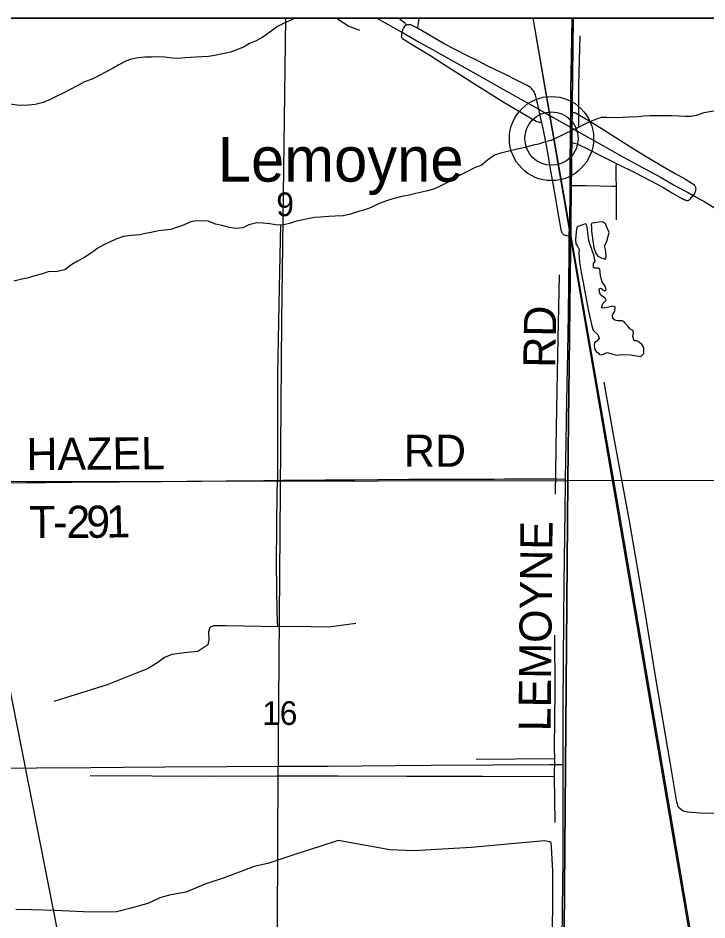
# Model space of a CAD drawing. Extents: x 0 to 34, y 0 to 22.
# Drawn here: x 3.546 to 4.765, y 19.306 to 20.9 of the extents above; entities that cross this region are included whole.
import ezdxf

# ---------------------------------------------------------------- set-up
doc = ezdxf.new("R2010")
doc.units = 0
for name, color, linetype in [('GM_X_City_Street', 7, 'Continuous'), ('GM_X_Minor_Lake', 7, 'Continuous'), ('GM_X_Minor_River', 7, 'Continuous'), ('GM_X_Rail_Line', 7, 'Continuous'), ('GM_X_Section', 7, 'Continuous'), ('GM_X_Section_Text', 7, 'Continuous'), ('GM_X_Township_Road', 7, 'Continuous'), ('GM_X_Township_Road_Text', 7, 'Continuous'), ('GM_X_Unincorporated', 7, 'Continuous'), ('GM_X_Unincorporated_Location', 7, 'Continuous'), ('GM_X_Unincorporated_Text', 7, 'Continuous'), ('GM_X_US_Route', 7, 'Continuous'), ('SH_Cut_Line', 7, 'Continuous'), ('SH_Data', 7, 'Continuous')]:
    doc.layers.add(name, color=color, linetype=linetype)

msp = doc.modelspace()

# ---------------------------------------------------------------- linework, layer by layer
at = {"layer": 'GM_X_City_Street'}
for points in [[(4.528, 20.9), (3.5146, 20.9), (3.5083, 20.0811), (4.5187, 20.0828)], [(5.527, 20.9), (4.528, 20.9), (4.5187, 20.0828), (5.5144, 20.0832)]]:
    msp.add_lwpolyline(points, close=True, dxfattribs=at)
at = {"layer": 'GM_X_Minor_Lake'}
for p, q in [((4.5559, 20.507), (4.5531, 20.5302)), ((4.5886, 20.5092), (4.5894, 20.5123))]:
    msp.add_line(p, q, dxfattribs=at)
for points in [[(4.5531, 20.5302), (4.5517, 20.5352), (4.5491, 20.5364), (4.5437, 20.5342), (4.5384, 20.5321), (4.5353, 20.531), (4.5341, 20.5269), (4.5331, 20.5159), (4.5325, 20.508), (4.5331, 20.5011), (4.5356, 20.4969), (4.5385, 20.4911), (4.5384, 20.485), (4.5385, 20.4763), (4.5395, 20.4687), (4.5424, 20.4508), (4.5458, 20.4325), (4.5491, 20.413), (4.5518, 20.4005), (4.5555, 20.3818), (4.5579, 20.3711), (4.5613, 20.3558), (4.5637, 20.3482), (4.5663, 20.3451), (4.5715, 20.3404), (4.574, 20.3335), (4.5697, 20.3291), (4.5662, 20.3265), (4.565, 20.3223), (4.566, 20.3155), (4.5689, 20.3105), (4.5722, 20.3081), (4.5748, 20.3054), (4.5789, 20.3045), (4.5885, 20.3089), (4.5983, 20.306), (4.6051, 20.3043), (4.6138, 20.3056), (4.6297, 20.3045), (4.6365, 20.3035), (4.6478, 20.3017), (4.6501, 20.3043), (4.6529, 20.3073), (4.6531, 20.3175), (4.6495, 20.323), (4.6446, 20.3272), (4.6402, 20.3296), (4.636, 20.3294), (4.6339, 20.3374), (4.6348, 20.3446), (4.6334, 20.3476), (4.6282, 20.3504), (4.6253, 20.3547), (4.6201, 20.3605), (4.6179, 20.3636), (4.6149, 20.3648), (4.6066, 20.365), (4.6021, 20.3662), (4.598, 20.369), (4.5977, 20.3754), (4.6017, 20.3818), (4.6023, 20.3897), (4.5985, 20.391), (4.5913, 20.3889), (4.5844, 20.3875), (4.5784, 20.3877), (4.5804, 20.3956), (4.5866, 20.4011), (4.5856, 20.4042), (4.5811, 20.407), (4.5766, 20.4105), (4.5745, 20.4159), (4.5739, 20.4216), (4.5773, 20.4226), (4.5836, 20.4179), (4.5867, 20.4201), (4.5846, 20.4259), (4.5795, 20.4336), (4.5764, 20.4446), (4.5761, 20.4511), (4.5755, 20.4564), (4.5721, 20.4577), (4.5661, 20.4578), (4.5642, 20.4594), (4.564, 20.4662), (4.5668, 20.4703), (4.5661, 20.4753), (4.5644, 20.4814), (4.5623, 20.4871), (4.5605, 20.4932), (4.5584, 20.499), (4.5559, 20.507)], [(4.5894, 20.5123), (4.5919, 20.5209), (4.5876, 20.5305), (4.5855, 20.5363), (4.5802, 20.5398), (4.5734, 20.5392), (4.5669, 20.5382), (4.5609, 20.5372), (4.56, 20.535), (4.5603, 20.53), (4.5605, 20.5236), (4.5618, 20.5152), (4.5627, 20.5061), (4.5647, 20.4943), (4.5665, 20.4893), (4.5672, 20.4859), (4.5715, 20.4789), (4.5779, 20.4761), (4.5847, 20.4737), (4.5863, 20.477), (4.5858, 20.4881), (4.5837, 20.4972), (4.5869, 20.504), (4.5886, 20.5092)]]:
    msp.add_lwpolyline(points, dxfattribs=at)
at = {"layer": 'GM_X_Minor_River'}
for points in [[(4.0361, 20.9), (4.0317, 20.8977), (4.0156, 20.8901), (4.0052, 20.885), (3.9917, 20.8751), (3.9794, 20.8659), (3.9675, 20.8598), (3.956, 20.8551), (3.946, 20.8489), (3.9364, 20.845), (3.9219, 20.8396), (3.9113, 20.8376), (3.8937, 20.8339), (3.8831, 20.8322), (3.8611, 20.8309), (3.8512, 20.83), (3.8414, 20.8298), (3.8304, 20.8286), (3.8198, 20.8292), (3.8054, 20.8311), (3.7945, 20.8313), (3.7827, 20.8309), (3.7706, 20.8308), (3.7588, 20.8295), (3.747, 20.8272), (3.7371, 20.8236), (3.7244, 20.8171), (3.7144, 20.8116), (3.701, 20.8044), (3.691, 20.7989), (3.6772, 20.792), (3.6638, 20.787), (3.6519, 20.7805), (3.6374, 20.7733), (3.6262, 20.7675), (3.6163, 20.7624), (3.6032, 20.7559), (3.591, 20.7509), (3.5765, 20.7474), (3.5655, 20.7458), (3.5496, 20.7454), (3.5269, 20.7486)], [(4.1103, 20.9), (4.1116, 20.8988), (4.1313, 20.8858), (4.1501, 20.8785)], [(4.5382, 20.7071), (4.5381, 20.7811), (4.5403, 20.8683)], [(4.7771, 20.7354), (4.7592, 20.7324), (4.7459, 20.7275), (4.736, 20.7262), (4.7261, 20.726), (4.7159, 20.7263), (4.7023, 20.727), (4.6879, 20.727), (4.675, 20.7269), (4.664, 20.7272), (4.6534, 20.7263), (4.6432, 20.7254), (4.628, 20.725), (4.6151, 20.7242), (4.6003, 20.7234), (4.5878, 20.7241), (4.5776, 20.7243), (4.5646, 20.7197), (4.5524, 20.7139), (4.5382, 20.7071), (4.5259, 20.7013), (4.5133, 20.6951), (4.4991, 20.6883), (4.4895, 20.6836), (4.4785, 20.6812), (4.467, 20.6769), (4.4575, 20.6752), (4.443, 20.6714)], [(4.443, 20.6714), (4.4289, 20.668), (4.4141, 20.6645), (4.4003, 20.6614), (4.3893, 20.6579), (4.3765, 20.6487), (4.3657, 20.6395), (4.3546, 20.636), (4.3427, 20.6291), (4.3332, 20.6247), (4.3217, 20.6193), (4.312, 20.6123), (4.3009, 20.6069), (4.2905, 20.6015), (4.281, 20.5975), (4.2707, 20.5947), (4.2604, 20.5923), (4.2501, 20.5896), (4.2383, 20.5872), (4.225, 20.5848), (4.209, 20.5807), (4.1983, 20.5768), (4.1853, 20.5721), (4.1707, 20.5649), (4.1581, 20.5603), (4.1486, 20.5579), (4.1345, 20.5533), (4.1211, 20.5505), (4.1075, 20.5501), (4.0961, 20.5493), (4.0813, 20.5481), (4.0711, 20.5476), (4.0615, 20.5455), (4.0505, 20.5431), (4.0391, 20.5408), (4.0265, 20.5369), (4.0162, 20.5345), (4.0045, 20.534), (3.9916, 20.5362), (3.9792, 20.5377), (3.9686, 20.5379), (3.9545, 20.5345), (3.9441, 20.5294), (3.9312, 20.5282), (3.9203, 20.5296), (3.9067, 20.5333), (3.8954, 20.5359), (3.8827, 20.5411), (3.8615, 20.5416), (3.852, 20.5396), (3.8374, 20.5335), (3.8267, 20.5296), (3.8164, 20.5264), (3.8058, 20.5248), (3.7948, 20.5239), (3.7818, 20.5212), (3.7716, 20.5192), (3.762, 20.5171), (3.7465, 20.5156), (3.7328, 20.5136), (3.7194, 20.509), (3.7079, 20.504), (3.698, 20.4989), (3.6876, 20.4931), (3.6745, 20.4839), (3.6629, 20.4759), (3.6514, 20.4704), (3.6414, 20.4646), (3.6291, 20.4547), (3.6154, 20.4523), (3.5995, 20.4516), (3.5899, 20.448), (3.5758, 20.4442), (3.5628, 20.44), (3.5529, 20.4383), (3.5388, 20.4352)], [(4.0105, 20.5343), (4.0081, 20.4235), (4.0051, 20.2706), (4.0054, 20.1438), (4.0052, 20.0892), (4.0038, 20.0646), (4.0029, 19.9367), (4.0041, 19.8486), (4.005, 19.8239)], [(4.4971, 20.0587), (4.4989, 20.1771), (4.5013, 20.3041), (4.5037, 20.446)], [(5.1098, 19.4913), (5.0582, 19.488), (4.9639, 19.4903), (4.8584, 19.4928), (4.7527, 19.4946), (4.7304, 19.4963), (4.7225, 19.4984), (4.7147, 19.5046), (4.7116, 19.5142), (4.6997, 19.5847), (4.6742, 19.733), (4.6549, 19.8537), (4.6284, 20.0077), (4.6, 20.1602), (4.5827, 20.2563)], [(4.1438, 19.8297), (4.0959, 19.8232), (4.0338, 19.8244), (4.005, 19.8239), (3.9456, 19.825), (3.914, 19.8257), (3.8918, 19.8255), (3.8853, 19.823), (3.8832, 19.8151), (3.8836, 19.8011), (3.8819, 19.7924), (3.8642, 19.7803), (3.8456, 19.7788), (3.8186, 19.7749), (3.8053, 19.77), (3.7936, 19.7611), (3.7752, 19.7498), (3.7511, 19.7405), (3.704, 19.7215), (3.6098, 19.6919)], [(4.4951, 19.809), (4.4957, 19.7115), (4.4947, 19.6094), (4.4953, 19.5904), (4.4945, 19.5586), (4.4959, 19.4784)], [(4.4953, 19.5904), (4.3563, 19.5896)], [(4.4945, 19.5586), (4.3692, 19.5593), (4.234, 19.5595), (4.1128, 19.5602), (4.0041, 19.5598), (3.8928, 19.5595), (3.6739, 19.5606)], [(4.4917, 19.233), (4.4923, 19.392), (4.49, 19.4353), (4.4894, 19.4422), (4.4868, 19.4441), (4.4773, 19.4455), (4.3475, 19.4338), (4.2463, 19.4279), (4.2039, 19.4301), (4.1123, 19.4464), (4.0802, 19.4358), (4.0394, 19.4227), (3.9882, 19.4057), (3.9642, 19.4006), (3.9111, 19.3806), (3.8801, 19.3704), (3.8434, 19.355), (3.8141, 19.35), (3.7973, 19.3451), (3.7762, 19.3349), (3.7458, 19.327), (3.7206, 19.32), (3.6748, 19.3199), (3.612, 19.3226), (3.5703, 19.324), (3.5427, 19.3243)]]:
    msp.add_lwpolyline(points, dxfattribs=at)
at = {"layer": 'GM_X_Rail_Line'}
for points in [[(3.0707, 20.9), (3.1351, 20.7649), (3.2934, 20.4339), (3.3742, 20.2628), (3.4243, 20.1498), (3.4485, 20.0723), (3.4792, 19.9786), (3.5083, 19.83), (3.6846, 18.9371), (3.8463, 18.1103), (4.0848, 16.8935)], [(4.0191, 20.9), (4.0122, 20.3656), (4.0051, 19.4649), (4.0042, 19.0681), (4.0247, 18.6307), (3.9918, 17.6084), (3.9918, 17.4265), (4.095, 16.8935)], [(5.5292, 14.4768), (5.5206, 14.546), (5.4959, 14.7503), (5.4725, 14.9371), (5.462, 15.0205), (5.4461, 15.156), (5.4028, 15.3982), (5.2961, 16.0228), (5.1204, 17.0387), (4.9909, 17.7947), (4.7368, 19.2661), (4.6073, 20.0278), (4.4575, 20.9)], [(5.5755, 14.1), (5.542, 14.3915), (5.5241, 14.5438), (5.4984, 14.7506), (5.475, 14.9374), (5.4645, 15.0208), (5.4485, 15.1564), (5.4052, 15.3987), (5.2986, 16.0233), (5.1228, 17.0391), (4.9933, 17.7951), (4.7392, 19.2665), (4.6097, 20.0282), (4.4576, 20.9)]]:
    msp.add_lwpolyline(points, dxfattribs=at)
at = {"layer": 'GM_X_Section'}
for points in [[(4.5187, 20.0828), (4.5106, 19.0706), (3.5044, 19.0749), (3.5083, 20.0811)], [(5.5144, 20.0832), (5.5091, 19.0615), (4.5106, 19.0706), (4.5187, 20.0828)]]:
    msp.add_lwpolyline(points, close=True, dxfattribs=at)
at = {"layer": 'GM_X_Township_Road'}
for points in [[(4.2333, 20.8876), (4.2315, 20.8899), (4.2309, 20.8907), (4.23, 20.8915), (4.2224, 20.8973), (4.2213, 20.8982), (4.2206, 20.899), (4.22, 20.8996), (4.2198, 20.9)], [(4.2528, 20.8819), (4.2542, 20.8869), (4.2548, 20.8903), (4.2554, 20.8945), (4.2556, 20.9)], [(4.5239, 20.734), (4.524, 20.7545), (4.524, 20.7725), (4.5247, 20.8035), (4.5253, 20.8308), (4.5265, 20.9)], [(4.2528, 20.8819), (4.2448, 20.8863), (4.2436, 20.8869), (4.2423, 20.8874), (4.241, 20.8878), (4.2395, 20.8881), (4.2383, 20.8882), (4.237, 20.8883), (4.2357, 20.8882), (4.2345, 20.888), (4.2333, 20.8876), (4.2325, 20.8872), (4.2317, 20.8866), (4.2311, 20.8862), (4.23, 20.885), (4.2288, 20.8834), (4.2279, 20.8821), (4.2273, 20.8809), (4.2266, 20.8795), (4.2261, 20.8781), (4.2251, 20.8752)], [(4.2251, 20.8752), (4.2244, 20.8697), (4.2243, 20.8683), (4.2242, 20.8674), (4.2244, 20.8665), (4.2247, 20.8657), (4.2252, 20.865), (4.2258, 20.8643), (4.2266, 20.8636), (4.2421, 20.854), (4.2538, 20.8469), (4.2745, 20.8341), (4.3018, 20.8168), (4.3291, 20.7995), (4.3521, 20.7847), (4.4044, 20.7521), (4.4444, 20.7281), (4.4628, 20.7177), (4.4641, 20.7171), (4.4655, 20.7167), (4.4665, 20.7164), (4.4678, 20.7161), (4.4693, 20.7158), (4.4727, 20.715)], [(4.4577, 20.7715), (4.4564, 20.7733), (4.4552, 20.7747), (4.454, 20.7759), (4.4526, 20.7772), (4.4512, 20.7783), (4.4498, 20.7792), (4.4468, 20.781), (4.4254, 20.7916), (4.4094, 20.7995), (4.3774, 20.8152), (4.3606, 20.8237), (4.339, 20.8346), (4.3217, 20.8433), (4.3002, 20.8547), (4.2528, 20.8819)], [(4.4727, 20.715), (4.4712, 20.7224), (4.4673, 20.7388), (4.4649, 20.7493), (4.4635, 20.7556), (4.4628, 20.7588), (4.4621, 20.7613), (4.4613, 20.7641), (4.4606, 20.7661), (4.4598, 20.768), (4.459, 20.7694), (4.4577, 20.7715)], [(4.5233, 20.6806), (4.5235, 20.6956), (4.5236, 20.7071), (4.5237, 20.7142), (4.5239, 20.734)], [(4.5239, 20.734), (4.5268, 20.7335), (4.529, 20.7331), (4.5307, 20.7328), (4.5314, 20.7326), (4.5321, 20.7324), (4.5327, 20.7321), (4.5337, 20.7317), (4.5494, 20.7227), (4.5642, 20.7137), (4.5778, 20.7053), (4.6298, 20.6726), (4.6468, 20.6615), (4.6631, 20.6515), (4.6822, 20.6404), (4.7086, 20.6251), (4.7268, 20.6152), (4.7399, 20.607), (4.7412, 20.6061), (4.7424, 20.6048), (4.7434, 20.6036), (4.744, 20.6025), (4.7444, 20.6013), (4.7447, 20.6), (4.7448, 20.5985), (4.7446, 20.5963), (4.7442, 20.594), (4.7435, 20.5919), (4.7427, 20.5901), (4.7404, 20.5864)], [(4.5209, 20.5143), (4.5169, 20.515), (4.5151, 20.5154), (4.5139, 20.5158), (4.5129, 20.5163), (4.5118, 20.5169), (4.5111, 20.5175), (4.5105, 20.5181), (4.51, 20.5186), (4.5093, 20.5194), (4.5088, 20.5202), (4.5083, 20.5211), (4.5078, 20.5223), (4.5074, 20.5237), (4.5069, 20.5259), (4.5029, 20.5493), (4.4975, 20.5804), (4.4933, 20.6043), (4.4905, 20.6207), (4.4877, 20.6365), (4.4839, 20.6591), (4.4794, 20.6842), (4.4742, 20.7076), (4.4727, 20.715)], [(4.5229, 20.604), (4.5229, 20.6266), (4.523, 20.6576), (4.5233, 20.6806)], [(4.5233, 20.6806), (4.5281, 20.6795), (4.5306, 20.6789), (4.5327, 20.6783), (4.535, 20.6775), (4.5568, 20.6669), (4.5739, 20.6582), (4.6024, 20.6441), (4.6045, 20.6431)], [(4.6045, 20.6028), (4.6043, 20.6181), (4.6042, 20.6313), (4.6044, 20.6372), (4.6045, 20.6431)], [(4.6045, 20.6431), (4.6386, 20.6263), (4.6766, 20.6062), (4.6885, 20.5997), (4.7041, 20.5906), (4.7161, 20.5836), (4.7209, 20.5809), (4.7225, 20.5801), (4.7238, 20.5796), (4.7254, 20.5789), (4.7271, 20.5783), (4.7285, 20.5779), (4.7295, 20.5777), (4.7306, 20.5776), (4.7316, 20.5777), (4.7325, 20.578), (4.7334, 20.5785), (4.7343, 20.5792), (4.7353, 20.58), (4.7404, 20.5864)], [(4.5218, 20.5321), (4.5223, 20.5532), (4.5227, 20.5793), (4.5229, 20.604)], [(4.5229, 20.604), (4.5283, 20.604), (4.5507, 20.6038), (4.575, 20.6033), (4.5975, 20.6029), (4.6045, 20.6028)], [(4.6048, 20.5432), (4.6047, 20.5729), (4.6047, 20.5965), (4.6045, 20.6028)], [(4.5209, 20.5143), (4.521, 20.5173), (4.5217, 20.529), (4.5218, 20.5321)], [(4.5147, 20.0852), (4.5154, 20.12), (4.5156, 20.1499), (4.5163, 20.1884), (4.5173, 20.2537), (4.5186, 20.309), (4.5196, 20.3774), (4.5205, 20.4296), (4.5208, 20.4874), (4.5208, 20.5104), (4.5209, 20.5143)], [(3.5189, 20.0783), (3.5608, 20.079), (3.5795, 20.0792), (3.595, 20.0793), (3.641, 20.0797), (3.725, 20.0804), (3.771, 20.0806), (3.8002, 20.0808), (3.8711, 20.0816), (3.9146, 20.0819), (3.9476, 20.0823), (4.0148, 20.0831), (4.0427, 20.0833), (4.0888, 20.0836), (4.1031, 20.0837), (4.1143, 20.0837), (4.1286, 20.0839), (4.1422, 20.0839), (4.1833, 20.0844), (4.2374, 20.0848), (4.2859, 20.0849), (4.3506, 20.0851), (4.3885, 20.0851), (4.4065, 20.0854), (4.4401, 20.0853), (4.4674, 20.0856), (4.4845, 20.0856), (4.4965, 20.0854), (4.5128, 20.0852), (4.5147, 20.0852)], [(4.5106, 19.5804), (4.5107, 19.604), (4.5105, 19.6799), (4.511, 19.765), (4.5116, 19.8365), (4.5124, 19.9011), (4.5136, 19.9851), (4.5141, 20.0324), (4.5145, 20.0747), (4.5147, 20.0852)], [(3.5035, 19.5744), (3.5059, 19.5744), (3.5793, 19.5747), (3.675, 19.5755), (3.7322, 19.5757), (3.8062, 19.5765), (3.9157, 19.5771), (4.0089, 19.5777), (4.0406, 19.5779), (4.0947, 19.578), (4.2135, 19.5787), (4.2763, 19.5792), (4.3864, 19.5799), (4.4865, 19.5805), (4.5039, 19.5804), (4.5106, 19.5804)], [(4.507, 19.0731), (4.5072, 19.0961), (4.5077, 19.1228), (4.5079, 19.1782), (4.5084, 19.2093), (4.5086, 19.2515), (4.5088, 19.2832), (4.5091, 19.3112), (4.5092, 19.3311), (4.5098, 19.364), (4.5103, 19.4175), (4.5103, 19.4598), (4.5105, 19.53), (4.5106, 19.5773), (4.5106, 19.5804)]]:
    msp.add_lwpolyline(points, dxfattribs=at)
at = {"layer": 'GM_X_Unincorporated'}
for radius in [0.0744, 0.0472]:
    msp.add_circle((4.4898, 20.687), radius, dxfattribs=at)
at = {"layer": 'GM_X_Unincorporated_Location'}
msp.add_line((4.4898, 20.687), (4.4898, 20.687), dxfattribs=at)
at = {"layer": 'GM_X_US_Route'}
msp.add_line((4.1808, 20.9), (4.2251, 20.8752), dxfattribs=at)
for points in [[(7.5667, 20.9), (2.1, 20.9)], [(4.2251, 20.8752), (4.2274, 20.8739), (4.256, 20.8576), (4.2836, 20.8419), (4.3709, 20.793), (4.405, 20.7737), (4.4517, 20.7476), (4.4673, 20.7388), (4.4929, 20.7245), (4.5236, 20.7071), (4.5378, 20.699), (4.5805, 20.6747), (4.6109, 20.6577), (4.6431, 20.6402), (4.6835, 20.6179), (4.707, 20.6047), (4.7257, 20.5944)], [(4.7257, 20.5944), (4.7302, 20.592), (4.7404, 20.5864)], [(4.7404, 20.5864), (4.7608, 20.5749), (4.7795, 20.5641), (4.7847, 20.5612)]]:
    msp.add_lwpolyline(points, dxfattribs=at)
at = {"layer": 'SH_Cut_Line'}
msp.add_lwpolyline([(7.5667, 20.9), (2.1, 20.9), (2.1, 14.1)], dxfattribs=at)
at = {"layer": 'SH_Data'}
msp.add_line((2.1, 20.9), (8.9, 20.9), dxfattribs=at)

# ---------------------------------------------------------------- texts
at = {"layer": 'GM_X_Section_Text'}
for s, height, p in [('9', 0.0419, (4.0031, 20.5498)), ('16', 0.04186, (3.9781, 19.6506))]:
    msp.add_text(s, height=height, rotation=0, dxfattribs=at).set_placement(p)
at = {"layer": 'GM_X_Township_Road_Text'}
for s, height, rotation, p in [('RD', 0.05682, 89.0245, (4.4966, 20.2815)), ('HAZEL', 0.05682, 0.4185, (3.5614, 20.1009)), ('RD', 0.05682, 0, (4.2289, 20.1068)), ('2', 0.0568, 0.3544, (3.632, 19.981)), ('9', 0.0568, 0.4988, (3.6672, 19.9812)), ('1', 0.0568, 1.2001, (3.7029, 19.9816)), ('T', 0.0568, 0.3, (3.5661, 19.9807)), ('-', 0.0568, 0.3179, (3.6086, 19.9809)), ('LEMOYNE', 0.05682, 89.4385, (4.4882, 19.6391))]:
    msp.add_text(s, height=height, rotation=rotation, dxfattribs=at).set_placement(p)
at = {"layer": 'GM_X_Unincorporated_Text'}
msp.add_text('Lemoyne', height=0.07898, rotation=0, dxfattribs=at).set_placement((3.8998, 20.6109))

doc.saveas('drawing.dxf')
